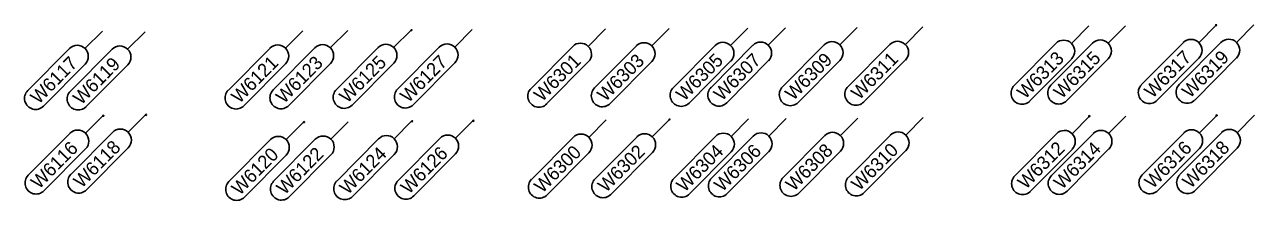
# Model space of a CAD drawing. Extents: x 12479652 to 12487250, y 9842710 to 9846560.
# Drawn here: x 12483761.3 to 12483876.1, y 9842746.3 to 9842762.7 of the extents above; entities that cross this region are included whole.
import ezdxf

# ---------------------------------------------------------------- set-up
doc = ezdxf.new("R2010")
doc.units = 0
doc.layers.add('_CIVIL_CONSTRUCTION', color=7, linetype='Continuous')
doc.layers.add('TextAlignmentLrg', color=7, linetype='Continuous')

msp = doc.modelspace()

# ---------------------------------------------------------------- linework, layer by layer
at = {"layer": '_CIVIL_CONSTRUCTION'}
for p, q in [((12483803.09, 9842762.2), (12483801.46, 9842760.57)), ((12483815.54, 9842762.27), (12483813.92, 9842760.64)), ((12483821.47, 9842762.31), (12483819.85, 9842760.68)), ((12483828.83, 9842762.35), (12483827.21, 9842760.72)), ((12483832.35, 9842762.37), (12483830.73, 9842760.74)), ((12483839.03, 9842762.41), (12483837.41, 9842760.78)), ((12483845.15, 9842762.45), (12483843.53, 9842760.82)), ((12483860.66, 9842762.54), (12483859.04, 9842760.91)), ((12483864.08, 9842762.56), (12483862.46, 9842760.93)), ((12483872.55, 9842762.62), (12483870.93, 9842760.98)), ((12483876.07, 9842762.64), (12483874.45, 9842761.01)), ((12483768.56, 9842762.07), (12483766.93, 9842760.43)), ((12483772.54, 9842762.01), (12483770.91, 9842760.38)), ((12483787.28, 9842762.1), (12483785.66, 9842760.47)), ((12483791.46, 9842762.13), (12483789.84, 9842760.49)), ((12483797.38, 9842762.16), (12483795.75, 9842760.53)), ((12483761.59, 9842756.52), (12483765.48, 9842760.43)), ((12483765.57, 9842756.46), (12483769.46, 9842760.38)), ((12483780.32, 9842756.55), (12483784.21, 9842760.47)), ((12483784.5, 9842756.58), (12483788.39, 9842760.49)), ((12483790.41, 9842756.61), (12483794.3, 9842760.53)), ((12483796.12, 9842756.65), (12483800.01, 9842760.56)), ((12483808.58, 9842756.72), (12483812.47, 9842760.64)), ((12483814.51, 9842756.76), (12483818.4, 9842760.67)), ((12483821.87, 9842756.8), (12483825.76, 9842760.72)), ((12483825.39, 9842756.82), (12483829.28, 9842760.74)), ((12483832.07, 9842756.87), (12483835.96, 9842760.78)), ((12483838.19, 9842756.9), (12483842.08, 9842760.81)), ((12483853.7, 9842757), (12483857.59, 9842760.91)), ((12483857.12, 9842757.02), (12483861.01, 9842760.93)), ((12483865.59, 9842757.07), (12483869.48, 9842760.98)), ((12483869.11, 9842757.09), (12483873, 9842761)), ((12483766.94, 9842758.98), (12483763.05, 9842755.07)), ((12483770.92, 9842758.93), (12483767.03, 9842755.02)), ((12483785.66, 9842759.02), (12483781.77, 9842755.11)), ((12483789.85, 9842759.04), (12483785.96, 9842755.13)), ((12483795.76, 9842759.08), (12483791.87, 9842755.17)), ((12483801.47, 9842759.11), (12483797.58, 9842755.2)), ((12483813.92, 9842759.19), (12483810.03, 9842755.28)), ((12483819.85, 9842759.23), (12483815.96, 9842755.31)), ((12483827.22, 9842759.27), (12483823.33, 9842755.36)), ((12483830.73, 9842759.29), (12483826.85, 9842755.38)), ((12483837.41, 9842759.33), (12483833.52, 9842755.42)), ((12483843.53, 9842759.37), (12483839.64, 9842755.46)), ((12483859.05, 9842759.46), (12483855.16, 9842755.55)), ((12483862.46, 9842759.48), (12483858.57, 9842755.57)), ((12483870.93, 9842759.53), (12483867.04, 9842755.62)), ((12483874.45, 9842759.56), (12483870.56, 9842755.64)), ((12483768.6, 9842754.17), (12483766.98, 9842752.54)), ((12483772.58, 9842754.26), (12483770.96, 9842752.63)), ((12483872.6, 9842754.2), (12483870.98, 9842752.57)), ((12483876.12, 9842754.23), (12483874.5, 9842752.59)), ((12483787.33, 9842753.58), (12483785.71, 9842751.95)), ((12483791.51, 9842753.61), (12483789.89, 9842751.98)), ((12483797.43, 9842753.66), (12483795.81, 9842752.02)), ((12483803.14, 9842753.7), (12483801.52, 9842752.07)), ((12483815.59, 9842753.79), (12483813.97, 9842752.16)), ((12483821.52, 9842753.83), (12483819.9, 9842752.2)), ((12483828.88, 9842753.88), (12483827.26, 9842752.25)), ((12483832.4, 9842753.91), (12483830.78, 9842752.28)), ((12483839.08, 9842753.96), (12483837.46, 9842752.33)), ((12483845.2, 9842754), (12483843.58, 9842752.37)), ((12483860.71, 9842754.13), (12483859.09, 9842752.49)), ((12483864.13, 9842754.14), (12483862.51, 9842752.51)), ((12483761.64, 9842748.62), (12483765.53, 9842752.53)), ((12483765.62, 9842748.71), (12483769.51, 9842752.62)), ((12483780.37, 9842748.03), (12483784.26, 9842751.95)), ((12483784.55, 9842748.06), (12483788.44, 9842751.98)), ((12483790.47, 9842748.11), (12483794.35, 9842752.02)), ((12483796.17, 9842748.15), (12483800.06, 9842752.06)), ((12483808.63, 9842748.24), (12483812.52, 9842752.15)), ((12483814.56, 9842748.28), (12483818.45, 9842752.19)), ((12483821.92, 9842748.33), (12483825.81, 9842752.25)), ((12483825.44, 9842748.36), (12483829.33, 9842752.27)), ((12483832.12, 9842748.41), (12483836.01, 9842752.32)), ((12483838.24, 9842748.45), (12483842.13, 9842752.37)), ((12483853.75, 9842748.58), (12483857.64, 9842752.49)), ((12483857.17, 9842748.59), (12483861.06, 9842752.5)), ((12483865.64, 9842748.65), (12483869.53, 9842752.56)), ((12483869.16, 9842748.68), (12483873.05, 9842752.59)), ((12483766.99, 9842751.09), (12483763.1, 9842747.17)), ((12483770.97, 9842751.18), (12483767.08, 9842747.26)), ((12483819.91, 9842750.75), (12483816.02, 9842746.83)), ((12483827.27, 9842750.8), (12483823.38, 9842746.89)), ((12483830.79, 9842750.83), (12483826.9, 9842746.91)), ((12483837.46, 9842750.87), (12483833.57, 9842746.96)), ((12483843.58, 9842750.92), (12483839.69, 9842747.01)), ((12483859.1, 9842751.04), (12483855.21, 9842747.13)), ((12483862.51, 9842751.06), (12483858.63, 9842747.14)), ((12483870.98, 9842751.12), (12483867.09, 9842747.21)), ((12483874.5, 9842751.14), (12483870.61, 9842747.23)), ((12483785.71, 9842750.5), (12483781.82, 9842746.59)), ((12483789.9, 9842750.53), (12483786.01, 9842746.62)), ((12483795.81, 9842750.57), (12483791.92, 9842746.66)), ((12483801.52, 9842750.61), (12483797.63, 9842746.7)), ((12483813.98, 9842750.7), (12483810.09, 9842746.79))]:
    msp.add_line(p, q, dxfattribs=at)
for centre, start, end in [((12483836.68, 9842760.05), 315.1702, 135.1702), ((12483842.8, 9842760.09), 315.1702, 135.1702), ((12483858.32, 9842760.19), 315.1702, 135.1702), ((12483861.74, 9842760.21), 315.1702, 135.1702), ((12483870.2, 9842760.26), 315.1702, 135.1702), ((12483873.72, 9842760.28), 315.1702, 135.1702), ((12483766.21, 9842759.71), 315.1702, 135.1702), ((12483770.19, 9842759.65), 315.1702, 135.1702), ((12483784.93, 9842759.74), 315.1702, 135.1702), ((12483789.12, 9842759.77), 315.1702, 135.1702), ((12483795.03, 9842759.8), 315.1702, 135.1702), ((12483800.74, 9842759.84), 315.1702, 135.1702), ((12483813.2, 9842759.91), 315.1702, 135.1702), ((12483819.13, 9842759.95), 315.1702, 135.1702), ((12483826.49, 9842759.99), 315.1702, 135.1702), ((12483830.01, 9842760.01), 315.1702, 135.1702), ((12483762.32, 9842755.79), 135.1702, 315.1702), ((12483766.3, 9842755.74), 135.1702, 315.1702), ((12483781.04, 9842755.83), 135.1702, 315.1702), ((12483785.23, 9842755.85), 135.1702, 315.1702), ((12483791.14, 9842755.89), 135.1702, 315.1702), ((12483796.85, 9842755.92), 135.1702, 315.1702), ((12483809.31, 9842756), 135.1702, 315.1702), ((12483815.24, 9842756.04), 135.1702, 315.1702), ((12483822.6, 9842756.08), 135.1702, 315.1702), ((12483826.12, 9842756.1), 135.1702, 315.1702), ((12483832.79, 9842756.14), 135.1702, 315.1702), ((12483838.91, 9842756.18), 135.1702, 315.1702), ((12483854.43, 9842756.27), 135.1702, 315.1702), ((12483857.85, 9842756.29), 135.1702, 315.1702), ((12483866.31, 9842756.34), 135.1702, 315.1702), ((12483869.84, 9842756.37), 135.1702, 315.1702), ((12483766.26, 9842751.81), 315.1702, 135.1702), ((12483770.24, 9842751.9), 315.1702, 135.1702), ((12483784.98, 9842751.22), 315.1702, 135.1702), ((12483789.17, 9842751.25), 315.1702, 135.1702), ((12483795.08, 9842751.3), 315.1702, 135.1702), ((12483800.79, 9842751.34), 315.1702, 135.1702), ((12483813.25, 9842751.43), 315.1702, 135.1702), ((12483819.18, 9842751.47), 315.1702, 135.1702), ((12483826.54, 9842751.52), 315.1702, 135.1702), ((12483830.06, 9842751.55), 315.1702, 135.1702), ((12483836.73, 9842751.6), 315.1702, 135.1702), ((12483842.85, 9842751.64), 315.1702, 135.1702), ((12483858.37, 9842751.77), 315.1702, 135.1702), ((12483861.79, 9842751.78), 315.1702, 135.1702), ((12483870.25, 9842751.84), 315.1702, 135.1702), ((12483873.78, 9842751.87), 315.1702, 135.1702), ((12483762.37, 9842747.9), 135.1702, 315.1702), ((12483766.35, 9842747.99), 135.1702, 315.1702), ((12483838.96, 9842747.73), 135.1702, 315.1702), ((12483854.48, 9842747.85), 135.1702, 315.1702), ((12483857.9, 9842747.87), 135.1702, 315.1702), ((12483866.37, 9842747.93), 135.1702, 315.1702), ((12483869.89, 9842747.95), 135.1702, 315.1702), ((12483781.1, 9842747.31), 135.1702, 315.1702), ((12483785.28, 9842747.34), 135.1702, 315.1702), ((12483791.19, 9842747.38), 135.1702, 315.1702), ((12483796.9, 9842747.42), 135.1702, 315.1702), ((12483809.36, 9842747.52), 135.1702, 315.1702), ((12483815.29, 9842747.56), 135.1702, 315.1702), ((12483822.65, 9842747.61), 135.1702, 315.1702), ((12483826.17, 9842747.64), 135.1702, 315.1702), ((12483832.85, 9842747.69), 135.1702, 315.1702)]:
    msp.add_arc(centre, 1.03, start, end, dxfattribs=at)
at = {"layer": 'TextAlignmentLrg'}
for centre in [(12483797.43, 9842762.16), (12483872.55, 9842762.62), (12483768.65, 9842754.17), (12483772.63, 9842754.26), (12483860.71, 9842754.13), (12483872.6, 9842754.2), (12483787.38, 9842753.58), (12483797.48, 9842753.66), (12483803.19, 9842753.7), (12483821.52, 9842753.83)]:
    msp.add_circle(centre, 0.05, dxfattribs=at)

# ---------------------------------------------------------------- texts
at = {"layer": '_CIVIL_CONSTRUCTION'}
for s, p in [('W6305', (12483822.88, 9842755.46)), ('W6307', (12483826.4, 9842755.48)), ('W6309', (12483833.07, 9842755.52)), ('W6311', (12483839.22, 9842755.59)), ('W6313', (12483854.71, 9842755.65)), ('W6315', (12483858.13, 9842755.68)), ('W6317', (12483866.6, 9842755.73)), ('W6319', (12483870.11, 9842755.74)), ('W6117', (12483762.6, 9842755.18)), ('W6119', (12483766.58, 9842755.11)), ('W6121', (12483781.35, 9842755.24)), ('W6123', (12483785.51, 9842755.23)), ('W6125', (12483791.43, 9842755.27)), ('W6127', (12483797.13, 9842755.31)), ('W6301', (12483809.61, 9842755.41)), ('W6303', (12483815.52, 9842755.42)), ('W6116', (12483762.64, 9842747.27)), ('W6118', (12483766.62, 9842747.36)), ('W6120', (12483781.37, 9842746.68)), ('W6122', (12483785.57, 9842746.73)), ('W6124', (12483791.46, 9842746.75)), ('W6126', (12483797.17, 9842746.79)), ('W6300', (12483809.63, 9842746.89)), ('W6302', (12483815.58, 9842746.95)), ('W6304', (12483822.91, 9842746.98)), ('W6306', (12483826.44, 9842747.01)), ('W6308', (12483833.12, 9842747.06)), ('W6310', (12483839.24, 9842747.1)), ('W6312', (12483854.77, 9842747.25)), ('W6314', (12483858.16, 9842747.23)), ('W6316', (12483866.63, 9842747.3)), ('W6318', (12483870.16, 9842747.33))]:
    msp.add_text(s, height=1.25, rotation=45.1702, dxfattribs=at).set_placement(p)

doc.saveas('drawing.dxf')
